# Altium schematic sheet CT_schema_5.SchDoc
size 334 x 183 mm
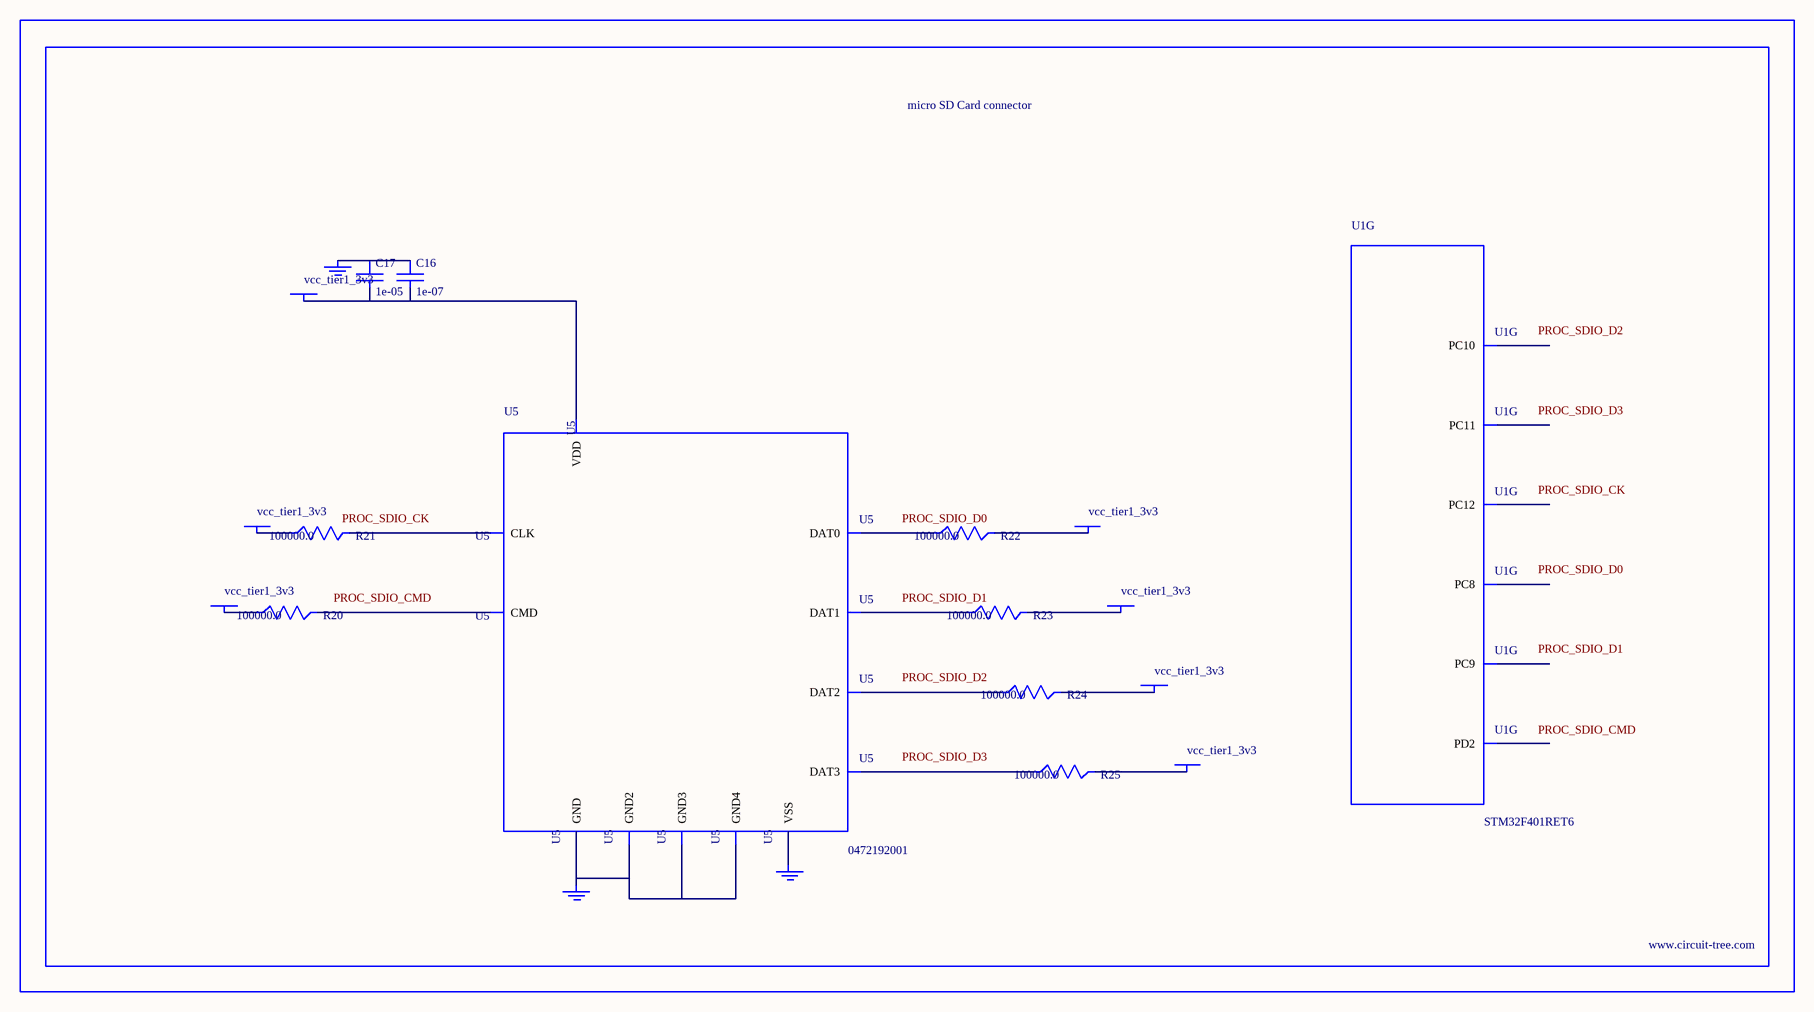
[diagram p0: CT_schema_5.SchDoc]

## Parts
BORDER4  (no value)
C16  1e-07  [C0402]
C17  1e-05  [C0805]
GND_INSTANCE_4_0  (no value)
GND_INSTANCE_4_1  (no value)
GND_INSTANCE_4_2  (no value)
POWER_INSTANCE_4_0  vcc_tier1_3v3
POWER_INSTANCE_4_1  vcc_tier1_3v3
POWER_INSTANCE_4_2  vcc_tier1_3v3
POWER_INSTANCE_4_3  vcc_tier1_3v3
POWER_INSTANCE_4_4  vcc_tier1_3v3
POWER_INSTANCE_4_5  vcc_tier1_3v3
POWER_INSTANCE_4_6  vcc_tier1_3v3
R20  100000.0  [R0603]
R21  100000.0  [R0603]
R22  100000.0  [R0603]
R23  100000.0  [R0603]
R24  100000.0  [R0603]
R25  100000.0  [R0603]
U1  STM32F401RET6  [LQFP64]  (part G of 7)
U5  0472192001  [MOLEX_47219-2001]

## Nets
NetC16_1: C16.1 C17.1 GND_INSTANCE_4_0.0(GND)
NetC16_2: C16.2 C17.2 POWER_INSTANCE_4_3.0(PWR) U5.4(VDD)
NetGND_INSTANCE_4_1_0: GND_INSTANCE_4_1.0(GND) U5.6(VSS)
NetGND_INSTANCE_4_2_0: GND_INSTANCE_4_2.0(GND) U5.G1(GND) U5.G2(GND2) U5.G3(GND3) U5.G4(GND4)
NetPOWER_INSTANCE_4_0_0: POWER_INSTANCE_4_0.0(PWR) R24.2
NetPOWER_INSTANCE_4_1_0: POWER_INSTANCE_4_1.0(PWR) R25.2
NetPOWER_INSTANCE_4_2_0: POWER_INSTANCE_4_2.0(PWR) R20.1
NetPOWER_INSTANCE_4_4_0: POWER_INSTANCE_4_4.0(PWR) R21.1
NetPOWER_INSTANCE_4_5_0: POWER_INSTANCE_4_5.0(PWR) R22.2
NetPOWER_INSTANCE_4_6_0: POWER_INSTANCE_4_6.0(PWR) R23.2
NetR20_2: R20.2 U5.3(CMD)
NetR21_2: R21.2 U5.5(CLK)
NetR22_1: R22.1 U5.7(DAT0)
NetR23_1: R23.1 U5.8(DAT1)
NetR24_1: R24.1 U5.1(DAT2)
NetR25_1: R25.1 U5.2(DAT3)

Not connected (* = marked no-connect by the designer): U1 39(PC8) 40(PC9) 51(PC10) 52(PC11) 53(PC12) 54(PD2)

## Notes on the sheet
- Labels drawn without touching a wire or pin: PROC_SDIO_CK, PROC_SDIO_CMD, PROC_SDIO_D0, PROC_SDIO_D1, PROC_SDIO_D2, PROC_SDIO_D3

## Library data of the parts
BORDER4 = BORDER_PAGE4
C16 = C0402C104K3RACTU
C17 = C0805C106K8RACTU
GND_INSTANCE_4_0-GND_INSTANCE_4_2 = GND
POWER_INSTANCE_4_0-POWER_INSTANCE_4_6 = PWR
R20-R25 = RC0603JR-07100KL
